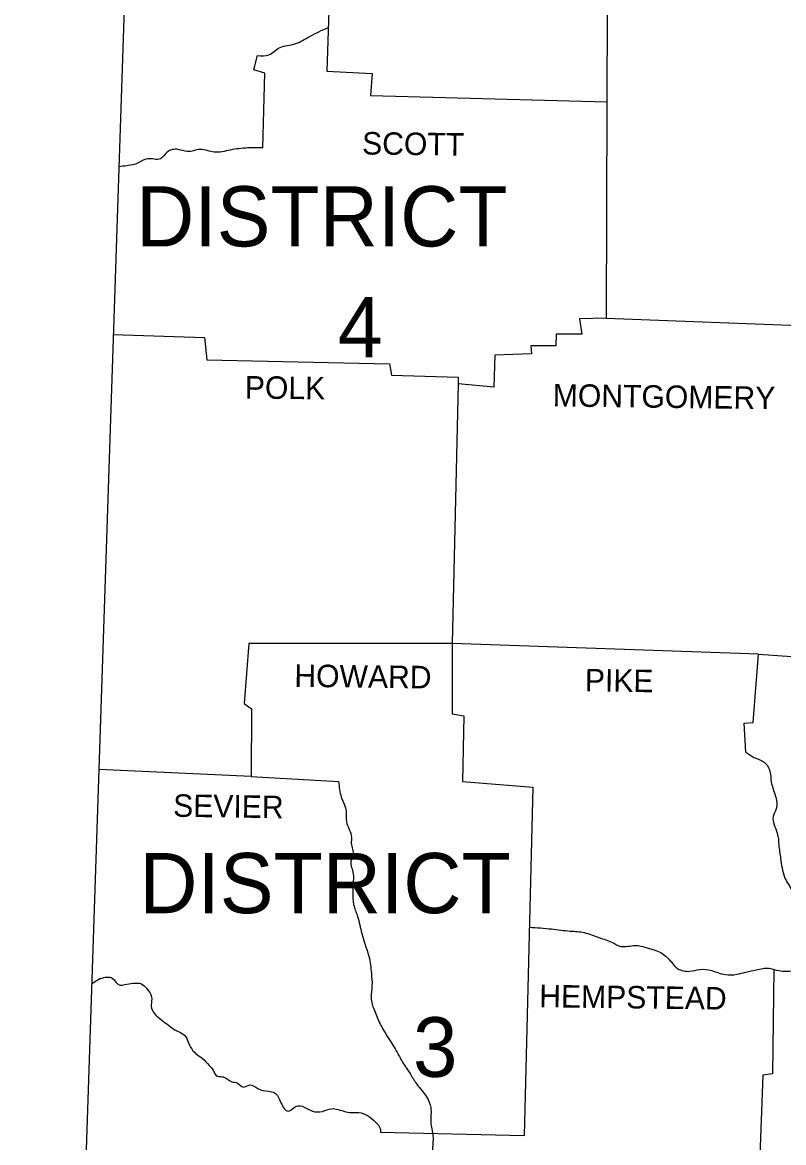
# Model space of a CAD drawing. Extents: x -0.96 to 2.36, y -0.12 to 0.92.
# Drawn here: x 1.0951 to 1.1608, y 0.624 to 0.7208 of the extents above; entities that cross this region are included whole.
import ezdxf

# ---------------------------------------------------------------- set-up
doc = ezdxf.new("R2010")
doc.units = 0
doc.layers.add('SHET_Annotations', color=7, linetype='Continuous')

msp = doc.modelspace()

# ---------------------------------------------------------------- linework, layer by layer
at = {"layer": 'SHET_Annotations'}
for p, q in [((1.103765, 0.708371), (1.103429, 0.708331)), ((1.101846, 0.638167), (1.101091, 0.637692))]:
    msp.add_line(p, q, dxfattribs=at)
for points in [[(1.095103, 0.817839), (1.104543, 0.741981), (1.100445, 0.618171)], [(1.14041, 0.741229), (1.140099, 0.73472), (1.13416, 0.734668), (1.133823, 0.728729), (1.127961, 0.728884), (1.12778, 0.72279), (1.121608, 0.722712), (1.1214, 0.716592), (1.125316, 0.716384), (1.125161, 0.714491), (1.145573, 0.71393)], [(1.17039, 0.734253), (1.170182, 0.727691), (1.159809, 0.72764), (1.158434, 0.726473), (1.15763, 0.724657), (1.156515, 0.724709), (1.156463, 0.723698), (1.155141, 0.723542), (1.155192, 0.722608), (1.148579, 0.722764), (1.14832, 0.722038), (1.145597, 0.721934), (1.145573, 0.71393)], [(1.115876, 0.709978), (1.116032, 0.71641), (1.115098, 0.716721), (1.115409, 0.71794)], [(1.145573, 0.71393), (1.145519, 0.695248), (1.143211, 0.695196), (1.143418, 0.693847), (1.141214, 0.693873), (1.141162, 0.692862), (1.139009, 0.692862), (1.139061, 0.692162), (1.135897, 0.692058), (1.13582, 0.689283), (1.132733, 0.689568), (1.132215, 0.667109)], [(1.145519, 0.695248), (1.163677, 0.694537)], [(1.102949, 0.693821), (1.110819, 0.693562), (1.111026, 0.691643), (1.126794, 0.691306), (1.126976, 0.69032), (1.132733, 0.690139), (1.132733, 0.689568)], [(1.158668, 0.666201), (1.132215, 0.667109), (1.114657, 0.667135), (1.114268, 0.661922), (1.114891, 0.661481), (1.114865, 0.65562), (1.101705, 0.656221)], [(1.132215, 0.667109), (1.132215, 0.661041), (1.133226, 0.660859), (1.133122, 0.655205), (1.139191, 0.654713), (1.138439, 0.624577), (1.126042, 0.624862)], [(1.157578, 0.657721), (1.157449, 0.660237), (1.158201, 0.660288), (1.158668, 0.666201), (1.16567, 0.665709), (1.165514, 0.662104), (1.174565, 0.661611), (1.174643, 0.659433), (1.182838, 0.65894), (1.184239, 0.656476), (1.183383, 0.655361), (1.183798, 0.653675), (1.204701, 0.65291)], [(1.114865, 0.65562), (1.122412, 0.655205)], [(1.15999, 0.638965), (1.159887, 0.62992), (1.159057, 0.629816), (1.158149, 0.605775)]]:
    msp.add_lwpolyline(points, dxfattribs=at)
for points in [[(1.115409, 0.71794), (1.116395, 0.718018), (1.117354, 0.71864), (1.118625, 0.718952), (1.119922, 0.7196), (1.121528, 0.72037)], [(1.115876, 0.709978), (1.114579, 0.709952), (1.113049, 0.709771), (1.111675, 0.709589), (1.110456, 0.709823), (1.109341, 0.709641), (1.108563, 0.709823), (1.107603, 0.709589), (1.107033, 0.709019), (1.105891, 0.709019), (1.105088, 0.708656), (1.103765, 0.708371)], [(1.157578, 0.657721), (1.158279, 0.65728), (1.15916, 0.656865), (1.159627, 0.656191), (1.159783, 0.655128), (1.16012, 0.653986), (1.160198, 0.652819), (1.159938, 0.652171), (1.160301, 0.650719), (1.160431, 0.649707), (1.160587, 0.64854), (1.160924, 0.646932), (1.16152, 0.645843), (1.162065, 0.64452), (1.162973, 0.643068), (1.163777, 0.641538), (1.16414, 0.640734), (1.164814, 0.639048), (1.16567, 0.637881), (1.16707, 0.636144), (1.168289, 0.634354), (1.168963, 0.633032), (1.170027, 0.631579), (1.17122, 0.630853), (1.172724, 0.630101), (1.173684, 0.629608), (1.174747, 0.62883), (1.176173, 0.628778), (1.177211, 0.628778), (1.178196, 0.628338), (1.178637, 0.627534), (1.179467, 0.626963), (1.180089, 0.626807)], [(1.122412, 0.655205), (1.122645, 0.653831), (1.12306, 0.652612), (1.123086, 0.65173), (1.123527, 0.650356), (1.123501, 0.649863), (1.123656, 0.648826), (1.123475, 0.648307), (1.123682, 0.647218), (1.123656, 0.646362), (1.12363, 0.645688), (1.123708, 0.644546), (1.124045, 0.643535), (1.124409, 0.642057), (1.124642, 0.641253), (1.125031, 0.64006), (1.125238, 0.638607), (1.12529, 0.637544), (1.125212, 0.636533), (1.125498, 0.635392), (1.12599, 0.634251), (1.126613, 0.633161), (1.127391, 0.631916), (1.127936, 0.630931), (1.12861, 0.629894), (1.129154, 0.629038), (1.13001, 0.627923), (1.130373, 0.627015), (1.130373, 0.62577), (1.130555, 0.624551), (1.130503, 0.623254), (1.130425, 0.622036), (1.130088, 0.620428), (1.130296, 0.61965), (1.131177, 0.618508), (1.131722, 0.618171), (1.132682, 0.61799), (1.133122, 0.617341), (1.133408, 0.616408), (1.134367, 0.616071), (1.135431, 0.615993), (1.135949, 0.615422), (1.136624, 0.614696), (1.137036, 0.614092)], [(1.138889, 0.642596), (1.140799, 0.642446), (1.142407, 0.642264), (1.143626, 0.642135), (1.144897, 0.641694), (1.146064, 0.641279), (1.14679, 0.640942), (1.148009, 0.641019), (1.149072, 0.640812), (1.150239, 0.640397), (1.151121, 0.639619), (1.151691, 0.639022), (1.152729, 0.638789), (1.15361, 0.638945), (1.154648, 0.638841), (1.155815, 0.638504), (1.1568, 0.63853), (1.157578, 0.638711), (1.158486, 0.638919), (1.159601, 0.639048), (1.160457, 0.638841), (1.161598, 0.638815), (1.162947, 0.638919), (1.164777, 0.639118)], [(1.101846, 0.638167), (1.102857, 0.638193), (1.103506, 0.637596), (1.103946, 0.637648), (1.104647, 0.637752), (1.105373, 0.6377), (1.10584, 0.637285), (1.106255, 0.636585), (1.106229, 0.635884), (1.106255, 0.635599), (1.106592, 0.635029), (1.107136, 0.634562), (1.107733, 0.634121), (1.108252, 0.633732), (1.109185, 0.633161), (1.109289, 0.63298), (1.109626, 0.632228), (1.110093, 0.631657), (1.110637, 0.631268), (1.111234, 0.630646), (1.111493, 0.63036), (1.11196, 0.629712), (1.112453, 0.62966), (1.113179, 0.629245), (1.113672, 0.629116), (1.11419, 0.628778), (1.114735, 0.62896), (1.115435, 0.628649), (1.116343, 0.628415), (1.116862, 0.628286), (1.117432, 0.62743), (1.118055, 0.626704), (1.118755, 0.627119), (1.120155, 0.626704), (1.121011, 0.626678), (1.121789, 0.626911), (1.122386, 0.626833), (1.123475, 0.626574), (1.124149, 0.626574), (1.124901, 0.626315), (1.125576, 0.62577), (1.126016, 0.625148), (1.126042, 0.624862)]]:
    msp.add_spline(points, degree=3, dxfattribs=at)

# ---------------------------------------------------------------- texts
for s, rotation, p in [('SCOTT', 359.31996, (1.124429, 0.709393)), ('POLK', 359.32331, (1.114305, 0.6883)), ('MONTGOMERY', 359.27067, (1.140898, 0.687614)), ('HOWARD', 359.30301, (1.118579, 0.663377)), ('PIKE', 359.17368, (1.143668, 0.662988)), ('SEVIER', 359.18154, (1.108108, 0.652148)), ('HEMPSTEAD', 359.25715, (1.139728, 0.635679))]:
    msp.add_text(s, height=0.0019451, rotation=rotation, dxfattribs=at).set_placement(p)
for s, height, p in [('DISTRICT', 0.0052027, (1.104925, 0.701443)), ('4', 0.005203, (1.122339, 0.691859)), ('DISTRICT', 0.0052027, (1.105194, 0.643809)), ('3', 0.005157, (1.128836, 0.629661))]:
    msp.add_text(s, height=height, dxfattribs=at).set_placement(p)

doc.saveas('drawing.dxf')
